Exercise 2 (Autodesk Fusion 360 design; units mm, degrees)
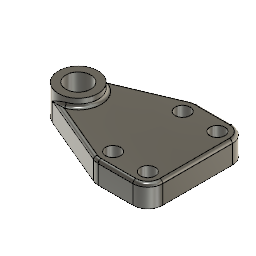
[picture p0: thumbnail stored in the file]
sketch "Sketch1" plane through (0, 0, 0) normal (0, 0, 1) x axis (1, 0, 0)
  line L1 (91.7315, 0) -> (0, 0)
  line L2 (64.1626, 48.8176) -> (-7.7831, 18.4234)
  line L3 (105, 50) -> (70, 50)
  line L4 (120, -35) -> (120, 35)
  line L5 (70, -50) -> (105, -50)
  line L6 (-7.7831, -18.4234) -> (64.1626, -48.8176)
  arc A1 centre (0, 0) radius 20 clockwise from (-7.7831, -18.4234) to (-7.7831, 18.4234)
  arc A2 centre (70, 35) radius 15 clockwise from (64.1626, 48.8176) to (70, 50)
  arc A3 centre (105, 35) radius 15 clockwise from (105, 50) to (120, 35)
  arc A4 centre (105, -35) radius 15 clockwise from (120, -35) to (105, -50)
  arc A5 centre (70, -35) radius 15 clockwise from (70, -50) to (64.1626, -48.8176)
  point P1 (0, 0)
  point P2 (0, 0)
  point P3 (0, 0)
  point P9 (70, 35)
  point P12 (105, 35)
  coincident P1 P2
  coincident P1 P3
  horizontal L1
  horizontal L3
  perpendicular L3 L4
  tangent L6 A1
  tangent L2 A1
  horizontal L5
  tangent L3 A2
  tangent L2 A2
  tangent L4 A3
  tangent L3 A3
  equal A2 A3
  tangent L4 A4
  tangent L5 A4
  equal A2 A4
  tangent L5 A5
  tangent L6 A5
  equal A2 A5
  symmetric L1 L3 L5
  equal L3 L5
  dimension "d2" distance L3 L5 = 100
  dimension "d4" radius A1 = 20
  dimension "d6" distance P2 L4 = 120
  dimension "d41" radius A2 = 15
  dimension "d42" distance P9 P12 = 35
extrude "Extrude1" new body sketch "Sketch1" profile of A1 L2 L3 L4 L5 L6 along normal blind 22
sketch "Sketch3" plane through (0, 0, 22) normal (0, 0, 1) x axis (-1, 0, 0)
  line L1 (-120, -35) -> (-120, 35)
  line L2 (-70, -50) -> (-105, -50)
  line L3 (7.7831, -18.4234) -> (-64.1626, -48.8176)
  line L4 (-64.1626, 48.8176) -> (7.7831, 18.4234)
  line L5 (-105, 50) -> (-70, 50)
  arc A1 centre (0, 0) radius 20 clockwise from (7.7831, 18.4234) to (7.7831, -18.4234)
  circle C1 centre (0, 0) radius 20
  arc A2 centre (-70, 35) radius 15 clockwise from (-70, 50) to (-64.1626, 48.8176)
  arc A3 centre (-105, 35) radius 15 clockwise from (-120, 35) to (-105, 50)
  arc A4 centre (-105, -35) radius 15 clockwise from (-105, -50) to (-120, -35)
  arc A5 centre (-70, -35) radius 15 clockwise from (-64.1626, -48.8176) to (-70, -50)
  point P1 (0, 0)
  point P13 (0, 0)
  coincident P1 P13
  dimension "d32" diameter C1 = 40
extrude "Extrude2" add sketch "Sketch3" profile of A1 C1 along normal blind 8
hole "Hole4" HoleDepth 22 HoleDiameter 15 TipAngle 180
hole "Hole5" HoleDepth 22 HoleDiameter 15 TipAngle 180
hole "Hole6" HoleDepth 22 HoleDiameter 15 TipAngle 180
hole "Hole7" HoleDepth 22 HoleDiameter 15 TipAngle 180
hole "Hole8" HoleDepth 30 HoleDiameter 25 TipAngle 180
shell "Shell1" innerThickness 5
fillet "Fillet2" radius 3
fillet "Fillet3" radius 3 3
